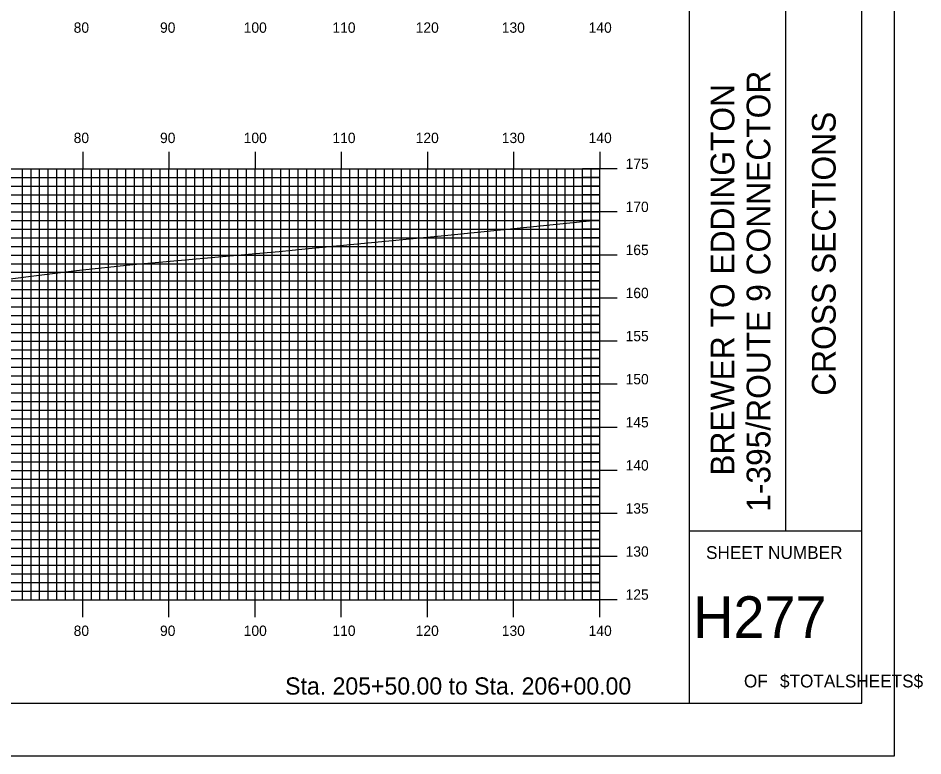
# Model space of a CAD drawing. Extents: x 1793272 to 1793615, y 442591 to 442811.
# Drawn here: x 1793510.3 to 1793615.3, y 442590.5 to 442676.2 of the extents above; entities that cross this region are included whole.
import ezdxf

# ---------------------------------------------------------------- set-up
doc = ezdxf.new("R2010")
doc.units = 0
for name, color, linetype in [('BORDER', 7, 'Continuous'), ('H_V ANNOTATION', 7, 'Continuous'), ('MAJOR', 7, 'Continuous'), ('MINOR', 7, 'Continuous'), ('PLOT BOUNDARY', 7, 'Continuous'), ('S_Roadway_Centerline', 7, 'Continuous')]:
    doc.layers.add(name, color=color, linetype=linetype)

msp = doc.modelspace()

# ---------------------------------------------------------------- linework, layer by layer
at = {"layer": 'BORDER'}
for p, q in [((1793588.2, 442596.67), (1793588.2, 442806.67)), ((1793599.38, 442616.67), (1793599.38, 442686.67)), ((1793588.2, 442616.67), (1793608.2, 442616.67))]:
    msp.add_line(p, q, dxfattribs=at)
msp.add_lwpolyline([(1793288.2, 442596.67), (1793608.2, 442596.67), (1793608.2, 442806.67), (1793288.2, 442806.67)], close=True, dxfattribs=at)
at = {"layer": 'MAJOR'}
for p, q in [((1793517.8, 442660.67), (1793517.8, 442658.67)), ((1793527.8, 442660.67), (1793527.8, 442658.67)), ((1793537.8, 442660.67), (1793537.8, 442658.67)), ((1793547.8, 442660.67), (1793547.8, 442658.67)), ((1793557.8, 442660.67), (1793557.8, 442658.67)), ((1793567.8, 442660.67), (1793567.8, 442658.67)), ((1793577.8, 442660.67), (1793577.8, 442658.67)), ((1793297.8, 442658.67), (1793577.8, 442658.67)), ((1793297.8, 442658.67), (1793577.8, 442658.67)), ((1793517.8, 442608.67), (1793517.8, 442658.67)), ((1793527.8, 442608.67), (1793527.8, 442658.67)), ((1793537.8, 442608.67), (1793537.8, 442658.67)), ((1793547.8, 442608.67), (1793547.8, 442658.67)), ((1793557.8, 442608.67), (1793557.8, 442658.67)), ((1793567.8, 442608.67), (1793567.8, 442658.67)), ((1793579.8, 442658.67), (1793575.8, 442658.67)), ((1793577.8, 442608.67), (1793577.8, 442658.67)), ((1793577.8, 442608.67), (1793577.8, 442658.67)), ((1793297.8, 442653.67), (1793577.8, 442653.67)), ((1793579.8, 442653.67), (1793575.8, 442653.67)), ((1793297.8, 442648.67), (1793577.8, 442648.67)), ((1793579.8, 442648.67), (1793575.8, 442648.67)), ((1793297.8, 442643.67), (1793577.8, 442643.67)), ((1793579.8, 442643.67), (1793575.8, 442643.67)), ((1793297.8, 442638.67), (1793577.8, 442638.67)), ((1793579.8, 442638.67), (1793575.8, 442638.67)), ((1793297.8, 442633.67), (1793577.8, 442633.67)), ((1793579.8, 442633.67), (1793575.8, 442633.67)), ((1793297.8, 442628.67), (1793577.8, 442628.67)), ((1793579.8, 442628.67), (1793575.8, 442628.67)), ((1793297.8, 442623.67), (1793577.8, 442623.67)), ((1793579.8, 442623.67), (1793575.8, 442623.67)), ((1793297.8, 442618.67), (1793577.8, 442618.67)), ((1793579.8, 442618.67), (1793575.8, 442618.67)), ((1793297.8, 442613.67), (1793577.8, 442613.67)), ((1793579.8, 442613.67), (1793575.8, 442613.67)), ((1793297.8, 442608.67), (1793577.8, 442608.67)), ((1793297.8, 442608.67), (1793577.8, 442608.67)), ((1793517.8, 442606.66), (1793517.8, 442608.67)), ((1793527.8, 442606.66), (1793527.8, 442608.67)), ((1793537.8, 442606.66), (1793537.8, 442608.67)), ((1793547.8, 442606.66), (1793547.8, 442608.67)), ((1793557.8, 442606.66), (1793557.8, 442608.67)), ((1793567.8, 442606.66), (1793567.8, 442608.67)), ((1793579.8, 442608.67), (1793575.8, 442608.67)), ((1793577.8, 442606.66), (1793577.8, 442608.67))]:
    msp.add_line(p, q, dxfattribs=at)
at = {"layer": 'MINOR'}
for p, q in [((1793510.8, 442608.67), (1793510.8, 442658.67)), ((1793511.8, 442608.67), (1793511.8, 442658.67)), ((1793512.8, 442608.67), (1793512.8, 442658.67)), ((1793513.8, 442608.67), (1793513.8, 442658.67)), ((1793514.8, 442608.67), (1793514.8, 442658.67)), ((1793515.8, 442608.67), (1793515.8, 442658.67)), ((1793516.8, 442608.67), (1793516.8, 442658.67)), ((1793518.8, 442608.67), (1793518.8, 442658.67)), ((1793519.8, 442608.67), (1793519.8, 442658.67)), ((1793520.8, 442608.67), (1793520.8, 442658.67)), ((1793521.8, 442608.67), (1793521.8, 442658.67)), ((1793522.8, 442608.67), (1793522.8, 442658.67)), ((1793523.8, 442608.67), (1793523.8, 442658.67)), ((1793524.8, 442608.67), (1793524.8, 442658.67)), ((1793525.8, 442608.67), (1793525.8, 442658.67)), ((1793526.8, 442608.67), (1793526.8, 442658.67)), ((1793528.8, 442608.67), (1793528.8, 442658.67)), ((1793529.8, 442608.67), (1793529.8, 442658.67)), ((1793530.8, 442608.67), (1793530.8, 442658.67)), ((1793531.8, 442608.67), (1793531.8, 442658.67)), ((1793532.8, 442608.67), (1793532.8, 442658.67)), ((1793533.8, 442608.67), (1793533.8, 442658.67)), ((1793534.8, 442608.67), (1793534.8, 442658.67)), ((1793535.8, 442608.67), (1793535.8, 442658.67)), ((1793536.8, 442608.67), (1793536.8, 442658.67)), ((1793538.8, 442608.67), (1793538.8, 442658.67)), ((1793539.8, 442608.67), (1793539.8, 442658.67)), ((1793540.8, 442608.67), (1793540.8, 442658.67)), ((1793541.8, 442608.67), (1793541.8, 442658.67)), ((1793542.8, 442608.67), (1793542.8, 442658.67)), ((1793543.8, 442608.67), (1793543.8, 442658.67)), ((1793544.8, 442608.67), (1793544.8, 442658.67)), ((1793545.8, 442608.67), (1793545.8, 442658.67)), ((1793546.8, 442608.67), (1793546.8, 442658.67)), ((1793548.8, 442608.67), (1793548.8, 442658.67)), ((1793549.8, 442608.67), (1793549.8, 442658.67)), ((1793550.8, 442608.67), (1793550.8, 442658.67)), ((1793551.8, 442608.67), (1793551.8, 442658.67)), ((1793552.8, 442608.67), (1793552.8, 442658.67)), ((1793553.8, 442608.67), (1793553.8, 442658.67)), ((1793554.8, 442608.67), (1793554.8, 442658.67)), ((1793555.8, 442608.67), (1793555.8, 442658.67)), ((1793556.8, 442608.67), (1793556.8, 442658.67)), ((1793558.8, 442608.67), (1793558.8, 442658.67)), ((1793559.8, 442608.67), (1793559.8, 442658.67)), ((1793560.8, 442608.67), (1793560.8, 442658.67)), ((1793561.8, 442608.67), (1793561.8, 442658.67)), ((1793562.8, 442608.67), (1793562.8, 442658.67)), ((1793563.8, 442608.67), (1793563.8, 442658.67)), ((1793564.8, 442608.67), (1793564.8, 442658.67)), ((1793565.8, 442608.67), (1793565.8, 442658.67)), ((1793566.8, 442608.67), (1793566.8, 442658.67)), ((1793568.8, 442608.67), (1793568.8, 442658.67)), ((1793569.8, 442608.67), (1793569.8, 442658.67)), ((1793570.8, 442608.67), (1793570.8, 442658.67)), ((1793571.8, 442608.67), (1793571.8, 442658.67)), ((1793572.8, 442608.67), (1793572.8, 442658.67)), ((1793573.8, 442608.67), (1793573.8, 442658.67)), ((1793574.8, 442608.67), (1793574.8, 442658.67)), ((1793575.8, 442608.67), (1793575.8, 442658.67)), ((1793576.8, 442608.67), (1793576.8, 442658.67)), ((1793297.8, 442657.67), (1793577.8, 442657.67)), ((1793577.8, 442657.67), (1793575.8, 442657.67)), ((1793297.8, 442656.67), (1793577.8, 442656.67)), ((1793577.8, 442656.67), (1793575.8, 442656.67)), ((1793297.8, 442655.67), (1793577.8, 442655.67)), ((1793577.8, 442655.67), (1793575.8, 442655.67)), ((1793297.8, 442654.67), (1793577.8, 442654.67)), ((1793577.8, 442654.67), (1793575.8, 442654.67)), ((1793297.8, 442652.67), (1793577.8, 442652.67)), ((1793577.8, 442652.67), (1793575.8, 442652.67)), ((1793297.8, 442651.67), (1793577.8, 442651.67)), ((1793577.8, 442651.67), (1793575.8, 442651.67)), ((1793297.8, 442650.67), (1793577.8, 442650.67)), ((1793577.8, 442650.67), (1793575.8, 442650.67)), ((1793297.8, 442649.67), (1793577.8, 442649.67)), ((1793577.8, 442649.67), (1793575.8, 442649.67)), ((1793297.8, 442647.67), (1793577.8, 442647.67)), ((1793577.8, 442647.67), (1793575.8, 442647.67)), ((1793297.8, 442646.67), (1793577.8, 442646.67)), ((1793297.8, 442645.67), (1793577.8, 442645.67)), ((1793577.8, 442646.67), (1793575.8, 442646.67)), ((1793577.8, 442645.67), (1793575.8, 442645.67)), ((1793297.8, 442644.67), (1793577.8, 442644.67)), ((1793577.8, 442644.67), (1793575.8, 442644.67)), ((1793297.8, 442642.67), (1793577.8, 442642.67)), ((1793577.8, 442642.67), (1793575.8, 442642.67)), ((1793297.8, 442641.67), (1793577.8, 442641.67)), ((1793577.8, 442641.67), (1793575.8, 442641.67)), ((1793297.8, 442640.67), (1793577.8, 442640.67)), ((1793577.8, 442640.67), (1793575.8, 442640.67)), ((1793297.8, 442639.67), (1793577.8, 442639.67)), ((1793577.8, 442639.67), (1793575.8, 442639.67)), ((1793297.8, 442637.67), (1793577.8, 442637.67)), ((1793577.8, 442637.67), (1793575.8, 442637.67)), ((1793297.8, 442636.67), (1793577.8, 442636.67)), ((1793577.8, 442636.67), (1793575.8, 442636.67)), ((1793297.8, 442635.67), (1793577.8, 442635.67)), ((1793577.8, 442635.67), (1793575.8, 442635.67)), ((1793297.8, 442634.67), (1793577.8, 442634.67)), ((1793577.8, 442634.67), (1793575.8, 442634.67)), ((1793297.8, 442632.67), (1793577.8, 442632.67)), ((1793577.8, 442632.67), (1793575.8, 442632.67)), ((1793297.8, 442631.67), (1793577.8, 442631.67)), ((1793577.8, 442631.67), (1793575.8, 442631.67)), ((1793297.8, 442630.67), (1793577.8, 442630.67)), ((1793577.8, 442630.67), (1793575.8, 442630.67)), ((1793297.8, 442629.67), (1793577.8, 442629.67)), ((1793577.8, 442629.67), (1793575.8, 442629.67)), ((1793297.8, 442627.67), (1793577.8, 442627.67)), ((1793577.8, 442627.67), (1793575.8, 442627.67)), ((1793297.8, 442626.67), (1793577.8, 442626.67)), ((1793577.8, 442626.67), (1793575.8, 442626.67)), ((1793297.8, 442625.67), (1793577.8, 442625.67)), ((1793297.8, 442624.67), (1793577.8, 442624.67)), ((1793577.8, 442625.67), (1793575.8, 442625.67)), ((1793577.8, 442624.67), (1793575.8, 442624.67)), ((1793297.8, 442622.67), (1793577.8, 442622.67)), ((1793577.8, 442622.67), (1793575.8, 442622.67)), ((1793297.8, 442621.67), (1793577.8, 442621.67)), ((1793577.8, 442621.67), (1793575.8, 442621.67)), ((1793297.8, 442620.67), (1793577.8, 442620.67)), ((1793577.8, 442620.67), (1793575.8, 442620.67)), ((1793297.8, 442619.67), (1793577.8, 442619.67)), ((1793577.8, 442619.67), (1793575.8, 442619.67)), ((1793297.8, 442617.67), (1793577.8, 442617.67)), ((1793577.8, 442617.67), (1793575.8, 442617.67)), ((1793297.8, 442616.67), (1793577.8, 442616.67)), ((1793577.8, 442616.67), (1793575.8, 442616.67)), ((1793297.8, 442615.67), (1793577.8, 442615.67)), ((1793577.8, 442615.67), (1793575.8, 442615.67)), ((1793297.8, 442614.67), (1793577.8, 442614.67)), ((1793577.8, 442614.67), (1793575.8, 442614.67)), ((1793297.8, 442612.67), (1793577.8, 442612.67)), ((1793577.8, 442612.67), (1793575.8, 442612.67)), ((1793297.8, 442611.67), (1793577.8, 442611.67)), ((1793577.8, 442611.67), (1793575.8, 442611.67)), ((1793297.8, 442610.67), (1793577.8, 442610.67)), ((1793577.8, 442610.67), (1793575.8, 442610.67)), ((1793297.8, 442609.67), (1793577.8, 442609.67)), ((1793577.8, 442609.67), (1793575.8, 442609.67))]:
    msp.add_line(p, q, dxfattribs=at)
at = {"layer": 'PLOT BOUNDARY'}
msp.add_lwpolyline([(1793272.01, 442590.55), (1793612.01, 442590.55), (1793612.01, 442810.55), (1793272.01, 442810.55)], close=True, dxfattribs=at)
at = {"layer": 'S_Roadway_Centerline'}
msp.add_lwpolyline([(1793505.02, 442645.37), (1793517.09, 442646.88), (1793523.63, 442647.57), (1793539.19, 442648.97), (1793540.61, 442649.1), (1793543.63, 442649.38), (1793559.78, 442650.95), (1793577, 442652.68), (1793577.8, 442652.77)], dxfattribs=at)

# ---------------------------------------------------------------- texts
at = {"layer": 'BORDER'}
for s, p in [('1-395/ROUTE 9 CONNECTOR', (1793597.6, 442618.87)), ('BREWER TO EDDINGTON', (1793593.42, 442623.07)), ('CROSS SECTIONS', (1793605.17, 442632.34))]:
    msp.add_text(s, height=2.7557, rotation=90, dxfattribs=at).set_placement(p)
for s, height, p in [('SHEET NUMBER', 1.4905, (1793590.13, 442613.4)), ('H277', 4.839, (1793588.64, 442604.23)), ('OF', 1.491, (1793594.53, 442598.49)), ('$TOTALSHEETS$', 1.4905, (1793598.71, 442598.49))]:
    msp.add_text(s, height=height, dxfattribs=at).set_placement(p)
at = {"layer": 'H_V ANNOTATION'}
for s, height, p in [('80', 1.2, (1793516.75, 442674.47)), ('90', 1.2, (1793526.77, 442674.47)), ('100', 1.2, (1793536.48, 442674.47)), ('110', 1.2, (1793546.78, 442674.47)), ('120', 1.2, (1793556.44, 442674.47)), ('130', 1.2, (1793566.43, 442674.47)), ('140', 1.2, (1793576.51, 442674.47)), ('80', 1.2, (1793516.75, 442661.67)), ('90', 1.2, (1793526.77, 442661.67)), ('100', 1.2, (1793536.48, 442661.67)), ('110', 1.2, (1793546.78, 442661.67)), ('120', 1.2, (1793556.44, 442661.67)), ('130', 1.2, (1793566.43, 442661.67)), ('140', 1.2, (1793576.51, 442661.67)), ('175', 1.2, (1793580.8, 442658.67)), ('170', 1.2, (1793580.8, 442653.67)), ('165', 1.2, (1793580.8, 442648.67)), ('160', 1.2, (1793580.8, 442643.67)), ('155', 1.2, (1793580.8, 442638.67)), ('150', 1.2, (1793580.8, 442633.67)), ('145', 1.2, (1793580.8, 442628.67)), ('140', 1.2, (1793580.8, 442623.67)), ('135', 1.2, (1793580.8, 442618.67)), ('130', 1.2, (1793580.8, 442613.67)), ('125', 1.2, (1793580.8, 442608.67)), ('80', 1.2, (1793516.75, 442604.47)), ('90', 1.2, (1793526.77, 442604.47)), ('100', 1.2, (1793536.48, 442604.47)), ('110', 1.2, (1793546.78, 442604.47)), ('120', 1.2, (1793556.44, 442604.47)), ('130', 1.2, (1793566.43, 442604.47)), ('140', 1.2, (1793576.51, 442604.47)), ('Sta. 205+50.00 to Sta. 206+00.00', 2.0004, (1793541.29, 442597.66))]:
    msp.add_text(s, height=height, dxfattribs=at).set_placement(p)

doc.saveas('drawing.dxf')
